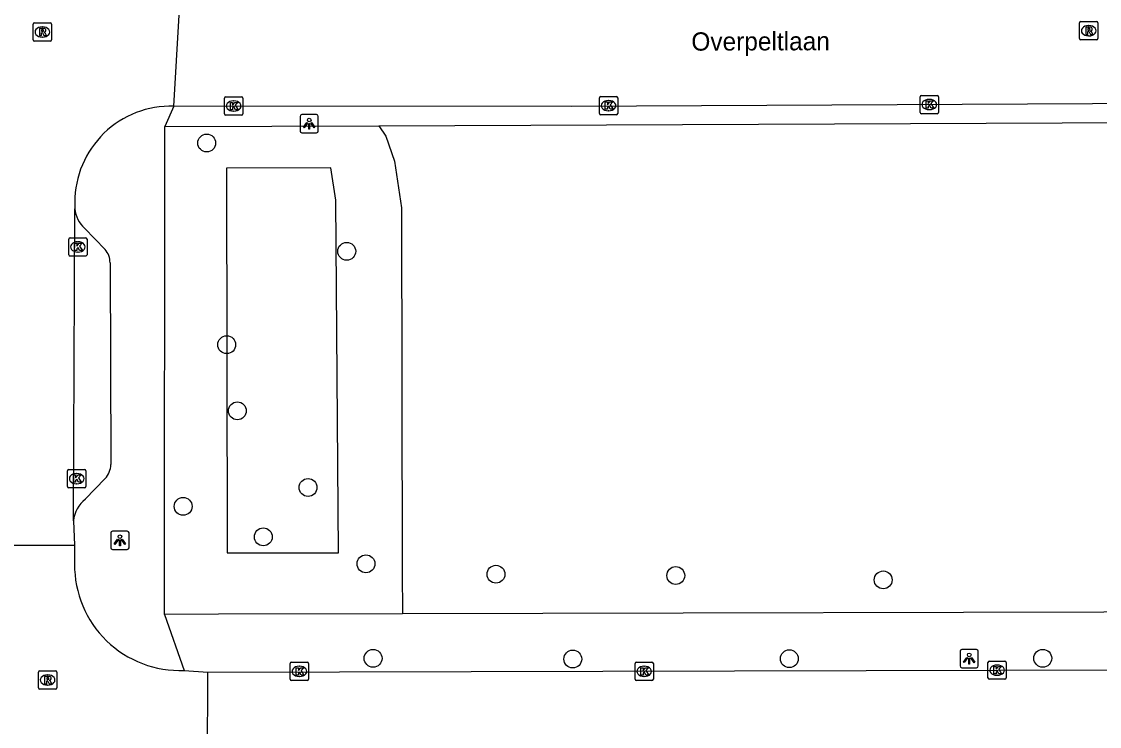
# Model space of a CAD drawing. Extents: x 160732 to 162105, y 387428 to 388479.
# Drawn here: x 161158.5 to 161217.5, y 388054.8 to 388093.4 of the extents above; entities that cross this region are included whole.
import ezdxf

# ---------------------------------------------------------------- set-up
doc = ezdxf.new("R2010")
doc.units = 0
for name, color, linetype in [('IMGEO_Boom', 7, 'Continuous'), ('IMGEO_Groenvoorziening', 7, 'Continuous'), ('IMGEO_Kolk', 7, 'Continuous'), ('IMGEO_Lichtpunt', 7, 'Continuous'), ('IMGEO_Openbare_ruimte_label', 7, 'Continuous'), ('IMGEO_Rijbaan_lokaal_open', 7, 'Continuous'), ('IMGEO_Rioolput', 7, 'Continuous'), ('IMGEO_Voetpad_open', 7, 'Continuous')]:
    doc.layers.add(name, color=color, linetype=linetype)

msp = doc.modelspace()

# ---------------------------------------------------------------- linework, layer by layer
at = {"layer": 'IMGEO_Boom'}
for centre in [(161168.619, 388086.743), (161176.283, 388080.814), (161169.714, 388075.702), (161170.295, 388072.084), (161174.165, 388067.888), (161167.328, 388066.854), (161171.715, 388065.183), (161177.336, 388063.71), (161184.452, 388063.138), (161194.293, 388063.067), (161205.648, 388062.828), (161177.725, 388058.535), (161188.655, 388058.497), (161200.51, 388058.514), (161214.381, 388058.537)]:
    msp.add_circle(centre, 0.489, dxfattribs=at)
at = {"layer": 'IMGEO_Groenvoorziening'}
for points in [[(161178.04, 388087.692), (161178.421, 388087.112), (161178.898, 388085.755), (161179.279, 388083.192), (161179.325, 388063.311), (161179.331, 388060.968)], [(161169.731, 388064.304), (161175.823, 388064.309), (161175.678, 388083.616), (161175.413, 388085.393), (161169.699, 388085.358), (161169.731, 388064.304)]]:
    msp.add_lwpolyline(points, dxfattribs=at)
at = {"layer": 'IMGEO_Kolk'}
for p, q in [((161207.747, 388089.348), (161208.599, 388089.348)), ((161169.592, 388088.34), (161169.592, 388089.192)), ((161169.667, 388089.266), (161170.519, 388089.266)), ((161170.08, 388089.046), (161170.105, 388089.046)), ((161170.593, 388089.192), (161170.593, 388088.34)), ((161190.115, 388088.363), (161190.115, 388089.215)), ((161190.19, 388089.289), (161191.042, 388089.289)), ((161190.603, 388089.069), (161190.628, 388089.069)), ((161191.116, 388089.215), (161191.116, 388088.363)), ((161207.672, 388088.422), (161207.672, 388089.274)), ((161208.16, 388089.128), (161208.185, 388089.128)), ((161208.673, 388089.274), (161208.673, 388088.422)), ((161170.519, 388088.266), (161169.667, 388088.266)), ((161170.103, 388088.486), (161170.078, 388088.486)), ((161191.042, 388088.289), (161190.19, 388088.289)), ((161190.626, 388088.509), (161190.601, 388088.509)), ((161208.599, 388088.348), (161207.747, 388088.348)), ((161208.183, 388088.568), (161208.158, 388088.568)), ((161161.066, 388080.629), (161161.066, 388081.481)), ((161161.141, 388081.555), (161161.993, 388081.555)), ((161161.554, 388081.335), (161161.579, 388081.335)), ((161162.067, 388081.481), (161162.067, 388080.629)), ((161161.993, 388080.555), (161161.141, 388080.555)), ((161161.577, 388080.775), (161161.552, 388080.775)), ((161161, 388067.947), (161161, 388068.799)), ((161161.075, 388068.873), (161161.927, 388068.873)), ((161162.001, 388068.799), (161162.001, 388067.947)), ((161161.511, 388068.093), (161161.486, 388068.093)), ((161161.488, 388068.653), (161161.513, 388068.653)), ((161161.927, 388067.873), (161161.075, 388067.873)), ((161173.19, 388057.395), (161173.19, 388058.247)), ((161173.265, 388058.321), (161174.117, 388058.321)), ((161173.678, 388058.101), (161173.703, 388058.101)), ((161174.191, 388058.247), (161174.191, 388057.395)), ((161192.065, 388057.395), (161192.065, 388058.247)), ((161192.14, 388058.321), (161192.992, 388058.321)), ((161192.553, 388058.101), (161192.578, 388058.101)), ((161193.066, 388058.247), (161193.066, 388057.395)), ((161211.381, 388057.462), (161211.381, 388058.314)), ((161211.456, 388058.388), (161212.308, 388058.388)), ((161211.869, 388058.168), (161211.894, 388058.168)), ((161212.382, 388058.314), (161212.382, 388057.462)), ((161173.701, 388057.541), (161173.676, 388057.541)), ((161192.576, 388057.541), (161192.551, 388057.541)), ((161211.892, 388057.608), (161211.867, 388057.608)), ((161174.117, 388057.321), (161173.265, 388057.321)), ((161192.992, 388057.321), (161192.14, 388057.321)), ((161212.308, 388057.388), (161211.456, 388057.388))]:
    msp.add_line(p, q, dxfattribs=at)
for points in [[(161207.747, 388089.348), (161208.599, 388089.348)], [(161169.592, 388088.34), (161169.592, 388089.192)], [(161169.667, 388089.266), (161170.519, 388089.266)], [(161169.913, 388088.966), (161170.036, 388088.966), (161170.036, 388088.815), (161170.166, 388088.966), (161170.33, 388088.966), (161170.184, 388088.815), (161170.337, 388088.566), (161170.185, 388088.566), (161170.1, 388088.73), (161170.036, 388088.663), (161170.036, 388088.566), (161169.913, 388088.566), (161169.913, 388088.966)], [(161170.593, 388089.192), (161170.593, 388088.34)], [(161190.115, 388088.363), (161190.115, 388089.215)], [(161190.19, 388089.289), (161191.042, 388089.289)], [(161190.436, 388088.989), (161190.559, 388088.989), (161190.559, 388088.838), (161190.689, 388088.989), (161190.853, 388088.989), (161190.707, 388088.838), (161190.86, 388088.589), (161190.708, 388088.589), (161190.623, 388088.753), (161190.559, 388088.686), (161190.559, 388088.589), (161190.436, 388088.589), (161190.436, 388088.989)], [(161191.116, 388089.215), (161191.116, 388088.363)], [(161207.672, 388088.422), (161207.672, 388089.274)], [(161207.993, 388089.048), (161208.116, 388089.048), (161208.116, 388088.897), (161208.246, 388089.048), (161208.41, 388089.048), (161208.264, 388088.897), (161208.417, 388088.648), (161208.265, 388088.648), (161208.18, 388088.812), (161208.116, 388088.745), (161208.116, 388088.648), (161207.993, 388088.648), (161207.993, 388089.048)], [(161208.673, 388089.274), (161208.673, 388088.422)], [(161170.519, 388088.266), (161169.667, 388088.266)], [(161191.042, 388088.289), (161190.19, 388088.289)], [(161208.599, 388088.348), (161207.747, 388088.348)], [(161161.066, 388080.629), (161161.066, 388081.481)], [(161161.141, 388081.555), (161161.993, 388081.555)], [(161161.387, 388081.255), (161161.51, 388081.255), (161161.51, 388081.104), (161161.64, 388081.255), (161161.804, 388081.255), (161161.658, 388081.104), (161161.811, 388080.855), (161161.659, 388080.855), (161161.574, 388081.019), (161161.51, 388080.952), (161161.51, 388080.855), (161161.387, 388080.855), (161161.387, 388081.255)], [(161162.067, 388081.481), (161162.067, 388080.629)], [(161161.993, 388080.555), (161161.141, 388080.555)], [(161161, 388067.947), (161161, 388068.799)], [(161161.075, 388068.873), (161161.927, 388068.873)], [(161162.001, 388068.799), (161162.001, 388067.947)], [(161161.321, 388068.573), (161161.444, 388068.573), (161161.444, 388068.422), (161161.574, 388068.573), (161161.738, 388068.573), (161161.592, 388068.422), (161161.745, 388068.173), (161161.593, 388068.173), (161161.508, 388068.337), (161161.444, 388068.27), (161161.444, 388068.173), (161161.321, 388068.173), (161161.321, 388068.573)], [(161161.927, 388067.873), (161161.075, 388067.873)], [(161173.19, 388057.395), (161173.19, 388058.247)], [(161173.265, 388058.321), (161174.117, 388058.321)], [(161174.191, 388058.247), (161174.191, 388057.395)], [(161192.065, 388057.395), (161192.065, 388058.247)], [(161192.14, 388058.321), (161192.992, 388058.321)], [(161193.066, 388058.247), (161193.066, 388057.395)], [(161211.381, 388057.462), (161211.381, 388058.314)], [(161211.456, 388058.388), (161212.308, 388058.388)], [(161211.702, 388058.088), (161211.825, 388058.088), (161211.825, 388057.937), (161211.955, 388058.088), (161212.119, 388058.088), (161211.973, 388057.937), (161212.126, 388057.688), (161211.974, 388057.688), (161211.889, 388057.852), (161211.825, 388057.785), (161211.825, 388057.688), (161211.702, 388057.688), (161211.702, 388058.088)], [(161212.382, 388058.314), (161212.382, 388057.462)], [(161173.511, 388058.021), (161173.634, 388058.021), (161173.634, 388057.87), (161173.764, 388058.021), (161173.928, 388058.021), (161173.782, 388057.87), (161173.935, 388057.621), (161173.783, 388057.621), (161173.698, 388057.785), (161173.634, 388057.718), (161173.634, 388057.621), (161173.511, 388057.621), (161173.511, 388058.021)], [(161192.386, 388058.021), (161192.509, 388058.021), (161192.509, 388057.87), (161192.639, 388058.021), (161192.803, 388058.021), (161192.657, 388057.87), (161192.81, 388057.621), (161192.658, 388057.621), (161192.573, 388057.785), (161192.509, 388057.718), (161192.509, 388057.621), (161192.386, 388057.621), (161192.386, 388058.021)], [(161174.117, 388057.321), (161173.265, 388057.321)], [(161192.992, 388057.321), (161192.14, 388057.321)], [(161212.308, 388057.388), (161211.456, 388057.388)]]:
    msp.add_lwpolyline(points, dxfattribs=at)
for centre, start, end in [((161207.749, 388089.272), 91.55205, 178.44795), ((161207.749, 388089.272), 91.55205, 178.44795), ((161208.597, 388089.272), 1.55205, 88.44795), ((161208.597, 388089.272), 1.55205, 88.44795), ((161169.669, 388089.19), 91.55205, 178.44795), ((161169.669, 388089.19), 91.55205, 178.44795), ((161170.517, 388089.19), 1.55205, 88.44795), ((161170.517, 388089.19), 1.55205, 88.44795), ((161190.192, 388089.213), 91.55205, 178.44795), ((161190.192, 388089.213), 91.55205, 178.44795), ((161191.04, 388089.213), 1.55205, 88.44795), ((161191.04, 388089.213), 1.55205, 88.44795), ((161169.669, 388088.342), 181.55205, 268.44795), ((161169.669, 388088.342), 181.55205, 268.44795), ((161170.517, 388088.342), 271.55205, 358.44795), ((161170.517, 388088.342), 271.55205, 358.44795), ((161190.192, 388088.365), 181.55205, 268.44795), ((161190.192, 388088.365), 181.55205, 268.44795), ((161191.04, 388088.365), 271.55205, 358.44795), ((161191.04, 388088.365), 271.55205, 358.44795), ((161207.749, 388088.424), 181.55205, 268.44795), ((161207.749, 388088.424), 181.55205, 268.44795), ((161208.597, 388088.424), 271.55205, 358.44795), ((161208.597, 388088.424), 271.55205, 358.44795), ((161161.143, 388081.479), 91.55205, 178.44795), ((161161.143, 388081.479), 91.55205, 178.44795), ((161161.991, 388081.479), 1.55205, 88.44795), ((161161.991, 388081.479), 1.55205, 88.44795), ((161161.143, 388080.631), 181.55205, 268.44795), ((161161.143, 388080.631), 181.55205, 268.44795), ((161161.991, 388080.631), 271.55205, 358.44795), ((161161.991, 388080.631), 271.55205, 358.44795), ((161161.077, 388068.797), 91.55205, 178.44795), ((161161.077, 388068.797), 91.55205, 178.44795), ((161161.925, 388068.797), 1.55205, 88.44795), ((161161.925, 388068.797), 1.55205, 88.44795), ((161161.077, 388067.949), 181.55205, 268.44795), ((161161.077, 388067.949), 181.55205, 268.44795), ((161161.925, 388067.949), 271.55205, 358.44795), ((161161.925, 388067.949), 271.55205, 358.44795), ((161173.267, 388058.245), 91.55205, 178.44795), ((161173.267, 388058.245), 91.55205, 178.44795), ((161174.115, 388058.245), 1.55205, 88.44795), ((161174.115, 388058.245), 1.55205, 88.44795), ((161192.142, 388058.245), 91.55205, 178.44795), ((161192.142, 388058.245), 91.55205, 178.44795), ((161192.99, 388058.245), 1.55205, 88.44795), ((161192.99, 388058.245), 1.55205, 88.44795), ((161211.458, 388058.312), 91.55205, 178.44795), ((161211.458, 388058.312), 91.55205, 178.44795), ((161212.306, 388058.312), 1.55205, 88.44795), ((161212.306, 388058.312), 1.55205, 88.44795), ((161173.267, 388057.397), 181.55205, 268.44795), ((161173.267, 388057.397), 181.55205, 268.44795), ((161174.115, 388057.397), 271.55205, 358.44795), ((161174.115, 388057.397), 271.55205, 358.44795), ((161192.142, 388057.397), 181.55205, 268.44795), ((161192.142, 388057.397), 181.55205, 268.44795), ((161192.99, 388057.397), 271.55205, 358.44795), ((161192.99, 388057.397), 271.55205, 358.44795), ((161211.458, 388057.464), 181.55205, 268.44795), ((161211.458, 388057.464), 181.55205, 268.44795), ((161212.306, 388057.464), 271.55205, 358.44795), ((161212.306, 388057.464), 271.55205, 358.44795)]:
    msp.add_arc(centre, 0.0765, start, end, dxfattribs=at)
for centre, major_axis, ratio, start_param, end_param in [((161170.079, 388088.766), (-0.387, 0.002), 0.722429, 4.712389, 7.853982), ((161170.104, 388088.766), (-0.39, 0.002), 0.717154, 1.570796, 4.712389), ((161190.602, 388088.789), (-0.387, 0.002), 0.722429, 4.712389, 7.853982), ((161190.627, 388088.789), (-0.39, 0.002), 0.717154, 1.570796, 4.712389), ((161208.159, 388088.848), (-0.387, 0.002), 0.722429, 4.712389, 7.853982), ((161208.184, 388088.848), (-0.39, 0.002), 0.717154, 1.570796, 4.712389), ((161161.553, 388081.055), (-0.387, 0.002), 0.722429, 4.712389, 7.853982), ((161161.578, 388081.055), (-0.39, 0.002), 0.717154, 1.570796, 4.712389), ((161161.487, 388068.373), (-0.387, 0.002), 0.722429, 4.712389, 7.853982), ((161161.512, 388068.373), (-0.39, 0.002), 0.717154, 1.570796, 4.712389), ((161173.677, 388057.821), (-0.387, 0.002), 0.722429, 4.712389, 7.853982), ((161173.702, 388057.821), (-0.39, 0.002), 0.717154, 1.570796, 4.712389), ((161192.552, 388057.821), (-0.387, 0.002), 0.722429, 4.712389, 7.853982), ((161192.577, 388057.821), (-0.39, 0.002), 0.717154, 1.570796, 4.712389), ((161211.868, 388057.888), (-0.387, 0.002), 0.722429, 4.712389, 7.853982), ((161211.893, 388057.888), (-0.39, 0.002), 0.717154, 1.570796, 4.712389)]:
    msp.add_ellipse(centre, major_axis=major_axis, ratio=ratio, start_param=start_param, end_param=end_param, dxfattribs=at)
at = {"layer": 'IMGEO_Lichtpunt'}
for p, q in [((161173.73, 388088.202), (161173.73, 388087.395)), ((161173.73, 388088.202), (161173.73, 388087.395)), ((161174.632, 388088.297), (161173.824, 388088.297)), ((161174.632, 388088.297), (161173.824, 388088.297)), ((161174.726, 388087.395), (161174.726, 388088.202)), ((161174.726, 388087.395), (161174.726, 388088.202)), ((161173.824, 388087.301), (161174.632, 388087.301)), ((161173.824, 388087.301), (161174.632, 388087.301)), ((161163.369, 388065.398), (161163.369, 388064.591)), ((161163.369, 388065.398), (161163.369, 388064.591)), ((161164.271, 388065.493), (161163.463, 388065.493)), ((161164.271, 388065.493), (161163.463, 388065.493)), ((161164.365, 388064.591), (161164.365, 388065.398)), ((161164.365, 388064.591), (161164.365, 388065.398)), ((161163.463, 388064.497), (161164.271, 388064.497)), ((161163.463, 388064.497), (161164.271, 388064.497)), ((161209.857, 388058.924), (161209.857, 388058.117)), ((161209.857, 388058.924), (161209.857, 388058.117)), ((161210.759, 388059.019), (161209.951, 388059.019)), ((161210.759, 388059.019), (161209.951, 388059.019)), ((161210.853, 388058.117), (161210.853, 388058.924)), ((161210.853, 388058.117), (161210.853, 388058.924)), ((161209.951, 388058.023), (161210.759, 388058.023)), ((161209.951, 388058.023), (161210.759, 388058.023))]:
    msp.add_line(p, q, dxfattribs=at)
for points in [[(161174.104, 388087.866), (161174.143, 388087.838), (161173.955, 388087.576), (161173.917, 388087.603), (161174.104, 388087.866)], [(161174.206, 388087.818), (161174.253, 388087.818), (161174.253, 388087.496), (161174.206, 388087.496), (161174.206, 388087.818)], [(161174.316, 388087.838), (161174.354, 388087.865), (161174.541, 388087.603), (161174.502, 388087.575), (161174.316, 388087.838)], [(161163.743, 388065.062), (161163.782, 388065.034), (161163.594, 388064.772), (161163.556, 388064.799), (161163.743, 388065.062)], [(161163.845, 388065.014), (161163.892, 388065.014), (161163.892, 388064.692), (161163.845, 388064.692), (161163.845, 388065.014)], [(161163.955, 388065.034), (161163.993, 388065.061), (161164.18, 388064.799), (161164.141, 388064.771), (161163.955, 388065.034)], [(161210.231, 388058.588), (161210.27, 388058.56), (161210.082, 388058.298), (161210.044, 388058.325), (161210.231, 388058.588)], [(161210.333, 388058.54), (161210.38, 388058.54), (161210.38, 388058.218), (161210.333, 388058.218), (161210.333, 388058.54)], [(161210.443, 388058.56), (161210.481, 388058.587), (161210.668, 388058.325), (161210.629, 388058.297), (161210.443, 388058.56)]]:
    msp.add_lwpolyline(points, dxfattribs=at)
for centre in [(161174.229, 388088), (161163.868, 388065.196), (161210.356, 388058.722)]:
    msp.add_circle(centre, 0.0994, dxfattribs=at)
for centre, start, end in [((161173.824, 388088.202), 90, 180), ((161173.824, 388088.202), 90, 180), ((161174.632, 388088.202), 0, 90), ((161174.632, 388088.202), 0, 90), ((161173.824, 388087.395), 180, 270), ((161173.824, 388087.395), 180, 270), ((161174.632, 388087.395), 270, 0), ((161174.632, 388087.395), 270, 360), ((161163.463, 388065.398), 90, 180), ((161163.463, 388065.398), 90, 180), ((161164.271, 388065.398), 0, 90), ((161164.271, 388065.398), 0, 90), ((161163.463, 388064.591), 180, 270), ((161163.463, 388064.591), 180, 270), ((161164.271, 388064.591), 270, 0), ((161164.271, 388064.591), 270, 360), ((161209.951, 388058.924), 90, 180), ((161209.951, 388058.924), 90, 180), ((161210.759, 388058.924), 0, 90), ((161210.759, 388058.924), 0, 90), ((161209.951, 388058.117), 180, 270), ((161209.951, 388058.117), 180, 270), ((161210.759, 388058.117), 270, 0), ((161210.759, 388058.117), 270, 360)]:
    msp.add_arc(centre, 0.0946, start, end, dxfattribs=at)
at = {"layer": 'IMGEO_Rijbaan_lokaal_open'}
for points in [[(161166.812, 388088.76), (161167.102, 388093.748)], [(161220.677, 388088.898), (161188.566, 388088.744), (161166.812, 388088.76)], [(161161.399, 388083.5), (161161.397, 388083.144)], [(161161.322, 388066.069), (161161.397, 388083.144)], [(161161.322, 388066.069), (161161.375, 388064.725)], [(161156.36, 388064.733), (161161.375, 388064.725)], [(161161.375, 388064.725), (161161.384, 388063.693)], [(161167.388, 388057.873), (161168.683, 388057.787)], [(161168.664, 388052.88), (161168.683, 388057.787)], [(161168.683, 388057.787), (161262.397, 388058.009)]]:
    msp.add_lwpolyline(points, dxfattribs=at)
for centre, radius, start, end in [((161166.658, 388083.504), 5.259, 88.31902, 180.03839), ((161167.154, 388063.638), 5.77, 179.4568, 272.32628)]:
    msp.add_arc(centre, radius, start, end, dxfattribs=at)
at = {"layer": 'IMGEO_Rioolput'}
for p, q in [((161159.12, 388092.393), (161159.12, 388093.245)), ((161159.195, 388093.319), (161160.047, 388093.319)), ((161159.608, 388093.099), (161159.633, 388093.099)), ((161160.121, 388093.245), (161160.121, 388092.393)), ((161216.396, 388092.463), (161216.396, 388093.315)), ((161216.471, 388093.389), (161217.323, 388093.389)), ((161216.884, 388093.169), (161216.909, 388093.169)), ((161217.397, 388093.315), (161217.397, 388092.463)), ((161160.047, 388092.319), (161159.195, 388092.319)), ((161159.631, 388092.539), (161159.606, 388092.539)), ((161217.323, 388092.389), (161216.471, 388092.389)), ((161216.907, 388092.609), (161216.882, 388092.609)), ((161159.409, 388056.922), (161159.409, 388057.774)), ((161159.484, 388057.848), (161160.336, 388057.848)), ((161159.897, 388057.628), (161159.922, 388057.628)), ((161160.41, 388057.774), (161160.41, 388056.922)), ((161159.92, 388057.068), (161159.895, 388057.068)), ((161160.336, 388056.848), (161159.484, 388056.848))]:
    msp.add_line(p, q, dxfattribs=at)
for points in [[(161159.12, 388092.393), (161159.12, 388093.245)], [(161159.195, 388093.319), (161160.047, 388093.319)], [(161159.709, 388093.017), (161159.457, 388093.019), (161159.457, 388092.619)], [(161159.635, 388092.938), (161159.581, 388092.938), (161159.581, 388092.857)], [(161160.121, 388093.245), (161160.121, 388092.393)], [(161216.396, 388092.463), (161216.396, 388093.315)], [(161216.471, 388093.389), (161217.323, 388093.389)], [(161216.985, 388093.087), (161216.733, 388093.089), (161216.733, 388092.689)], [(161216.911, 388093.008), (161216.857, 388093.008), (161216.857, 388092.927)], [(161216.857, 388092.927), (161216.909, 388092.927)], [(161217.397, 388093.315), (161217.397, 388092.463)], [(161160.047, 388092.319), (161159.195, 388092.319)], [(161159.457, 388092.619), (161159.581, 388092.619), (161159.581, 388092.781), (161159.592, 388092.781)], [(161159.581, 388092.857), (161159.633, 388092.857)], [(161159.639, 388092.752), (161159.71, 388092.619), (161159.85, 388092.619), (161159.785, 388092.745)], [(161217.323, 388092.389), (161216.471, 388092.389)], [(161216.733, 388092.689), (161216.857, 388092.689), (161216.857, 388092.851), (161216.868, 388092.851)], [(161216.915, 388092.822), (161216.986, 388092.689), (161217.126, 388092.689), (161217.061, 388092.815)], [(161159.409, 388056.922), (161159.409, 388057.774)], [(161159.484, 388057.848), (161160.336, 388057.848)], [(161159.998, 388057.546), (161159.746, 388057.548), (161159.746, 388057.148)], [(161160.41, 388057.774), (161160.41, 388056.922)], [(161159.746, 388057.148), (161159.87, 388057.148), (161159.87, 388057.31), (161159.881, 388057.31)], [(161159.924, 388057.467), (161159.87, 388057.467), (161159.87, 388057.386)], [(161159.87, 388057.386), (161159.922, 388057.386)], [(161159.928, 388057.281), (161159.999, 388057.148), (161160.139, 388057.148), (161160.074, 388057.274)], [(161160.336, 388056.848), (161159.484, 388056.848)]]:
    msp.add_lwpolyline(points, dxfattribs=at)
for centre, radius, start, end in [((161159.197, 388093.243), 0.0765, 91.55205, 178.44795), ((161159.197, 388093.243), 0.0765, 91.55205, 178.44795), ((161159.641, 388092.842), 0.0964, 77.00612, 93.18647), ((161159.655, 388092.899), 0.0378, 276.66336, 79.67722), ((161159.708, 388092.907), 0.109, 350.36119, 89.41601), ((161159.706, 388092.907), 0.112, 277.58423, 350.98172), ((161160.045, 388093.243), 0.0765, 1.55205, 88.44795), ((161160.045, 388093.243), 0.0765, 1.55205, 88.44795), ((161216.473, 388093.313), 0.0765, 91.55205, 178.44795), ((161216.473, 388093.313), 0.0765, 91.55205, 178.44795), ((161216.893, 388093.116), 0.19, 274.7715, 282.96867), ((161216.917, 388092.912), 0.0964, 77.00612, 93.18647), ((161216.931, 388092.969), 0.0378, 276.66336, 79.67722), ((161216.984, 388092.977), 0.109, 350.36119, 89.41601), ((161216.982, 388092.977), 0.112, 277.58423, 350.98172), ((161217.321, 388093.313), 0.0765, 1.55205, 88.44795), ((161217.321, 388093.313), 0.0765, 1.55205, 88.44795), ((161159.197, 388092.395), 0.0765, 181.55205, 268.44795), ((161159.197, 388092.395), 0.0765, 181.55205, 268.44795), ((161159.591, 388092.728), 0.0533, 26.02933, 88.69889), ((161159.617, 388093.046), 0.19, 274.7715, 282.96867), ((161159.69, 388092.692), 0.108, 29.51342, 73.79051), ((161160.045, 388092.395), 0.0765, 271.55205, 358.44795), ((161160.045, 388092.395), 0.0765, 271.55205, 358.44795), ((161216.473, 388092.465), 0.0765, 181.55205, 268.44795), ((161216.473, 388092.465), 0.0765, 181.55205, 268.44795), ((161216.867, 388092.798), 0.0533, 26.02933, 88.69889), ((161216.966, 388092.762), 0.108, 29.51342, 73.79051), ((161217.321, 388092.465), 0.0765, 271.55205, 358.44795), ((161217.321, 388092.465), 0.0765, 271.55205, 358.44795), ((161159.486, 388057.772), 0.0765, 91.55205, 178.44795), ((161159.486, 388057.772), 0.0765, 91.55205, 178.44795), ((161159.997, 388057.436), 0.109, 350.36119, 89.41601), ((161160.334, 388057.772), 0.0765, 1.55205, 88.44795), ((161160.334, 388057.772), 0.0765, 1.55205, 88.44795), ((161159.486, 388056.924), 0.0765, 181.55205, 268.44795), ((161159.486, 388056.924), 0.0765, 181.55205, 268.44795), ((161159.88, 388057.257), 0.0533, 26.02933, 88.69889), ((161159.906, 388057.575), 0.19, 274.7715, 282.96867), ((161159.93, 388057.371), 0.0964, 77.00612, 93.18647), ((161159.944, 388057.428), 0.0378, 276.66336, 79.67722), ((161159.995, 388057.436), 0.112, 277.58423, 350.98172), ((161159.979, 388057.221), 0.108, 29.51342, 73.79051), ((161160.334, 388056.924), 0.0765, 271.55205, 358.44795), ((161160.334, 388056.924), 0.0765, 271.55205, 358.44795)]:
    msp.add_arc(centre, radius, start, end, dxfattribs=at)
for centre, major_axis, ratio, start_param, end_param in [((161159.607, 388092.819), (-0.387, 0.002), 0.722429, 4.712389, 7.853982), ((161159.632, 388092.819), (-0.39, 0.002), 0.717154, 1.570796, 4.712389), ((161216.883, 388092.889), (-0.387, 0.002), 0.722429, 4.712389, 7.853982), ((161216.908, 388092.889), (-0.39, 0.002), 0.717154, 1.570796, 4.712389), ((161159.896, 388057.348), (-0.387, 0.002), 0.722429, 4.712389, 7.853982), ((161159.921, 388057.348), (-0.39, 0.002), 0.717154, 1.570796, 4.712389)]:
    msp.add_ellipse(centre, major_axis=major_axis, ratio=ratio, start_param=start_param, end_param=end_param, dxfattribs=at)
at = {"layer": 'IMGEO_Voetpad_open'}
for points in [[(161166.812, 388088.76), (161166.323, 388087.644)], [(161166.3, 388060.938), (161166.323, 388087.644)], [(161166.323, 388087.644), (161178.04, 388087.692)], [(161178.04, 388087.692), (161219.601, 388087.862)], [(161161.93, 388082.082), (161163.063, 388080.921)], [(161163.327, 388080.19), (161163.371, 388069.138)], [(161271.433, 388077.094), (161271.445, 388076.346), (161271.486, 388061.181), (161179.331, 388060.968)], [(161163.057, 388068.38), (161161.974, 388067.243)], [(161179.331, 388060.968), (161169.258, 388060.945), (161166.3, 388060.938)], [(161166.3, 388060.938), (161167.388, 388057.873)]]:
    msp.add_lwpolyline(points, dxfattribs=at)
for centre, radius, start, end in [((161163.06, 388083.314), 1.672, 185.83672, 227.4659), ((161162.185, 388080.191), 1.142, 359.95567, 39.75861), ((161162.223, 388069.17), 1.148, 316.56923, 358.4274), ((161163.062, 388065.871), 1.751, 128.40715, 173.50022)]:
    msp.add_arc(centre, radius, start, end, dxfattribs=at)

# ---------------------------------------------------------------- texts
at = {"layer": 'IMGEO_Openbare_ruimte_label'}
msp.add_text('Overpeltlaan', height=1, rotation=0.17189, dxfattribs=at).set_placement((161195.148, 388091.799))

doc.saveas('drawing.dxf')
